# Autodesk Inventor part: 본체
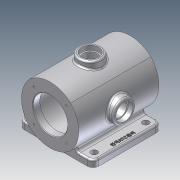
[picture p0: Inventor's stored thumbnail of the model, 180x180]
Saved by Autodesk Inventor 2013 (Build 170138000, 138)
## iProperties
Company: 한국ATC센터
Created: 2014-08
Part Number: 본체
Document SubType Name: Modeling
Designer: KYOUNG IL JANG
Density: 1 g/cm^3
Material: 일반
Mass: 1211.76 g
Surface Area: 1019.41 cm^2
Volume: 447.145 cm^3
Author: KYOUNG IL JANG
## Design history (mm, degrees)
sketch "스케치1"
  geometry: L1 (-50, 0)-(50, 0); L2 (-36.062, 36.062)-(36.062, 36.062); L3 (36.062, 36.062)-(36.062, -36.062); L4 (36.062, -36.062)-(-36.062, -36.062); L5 (-36.062, -36.062)-(-36.062, 36.062); A1 r 53.623 centre (-3.623, 0) between (36.062, -36.062) and (36.062, 36.062); A2 r 53.623 centre (3.623, 0) between (-36.062, 36.062) and (-36.062, -36.062); A3 r 53.623 centre (0, -3.623) between (36.062, 36.062) and (-36.062, 36.062); A4 r 53.623 centre (0, 3.623) between (-36.062, -36.062) and (36.062, -36.062); 4 further points
  constraints: 11 point on circle, 10 end point, 5 coincident, 4 centre point, 4 horizontal alignment, 3 equal radius, 2 horizontal, 2 parallel, 2 perpendicular, 1 midpoint
  dimensions: "d83" = 51 distance of L2.end point (0, 0); "d84" = 100 distance of L1.end L1.start
extrude "돌출1" new body sketch "스케치1" stored distance "d9" = 140; taper "d10" = 0 deg
node "작업 평면1"
sketch "스케치2"
  geometry: L1 (65, 60)-(-65, 60); L2 (-65, 60)-(-65, -60); L3 (-65, -60)-(65, -60); L4 (65, -60)-(65, 60); 4 further points
  constraints: 8 end point, 3 midpoint, 2 parallel, 2 vertical alignment, 1 horizontal, 1 horizontal alignment, 1 perpendicular
  dimensions: "d14" = 130 distance of L2.end L3.end; "d82" = 120 distance of L1.end L2.end
extrude "돌출2" join sketch "스케치2" distance "d15" = 12; taper "d16" = 0 deg
node "작업 평면3"
  node "작업 평면4"
sketch "스케치3"
  geometry: C1 r 20 at (0, 0); 1 further point
  constraints: 2 coincident, 1 centre point
  dimensions: "d19" = 40 diameter of C1
extrude "돌출3" join sketch "스케치3" stored distance "d23" = 12; taper "d24" = 0 deg
node "작업 평면6"
  node "작업 평면5"
sketch "스케치13"
  geometry: C1 r 20 at (0, 0); 1 further point
  constraints: 1 centre point, 1 coincident
  dimensions: "d88" = 40 diameter of C1
extrude "돌출7" join sketch "스케치13" stored distance "d89" = 10; taper "d90" = 0 deg
sketch "스케치4"
  geometry: C1 r 37.5 at (0, 0); 1 further point
  constraints: 1 centre point, 1 coincident
  dimensions: "d25" = 75 diameter of C1
extrude "돌출4" cut sketch "스케치4" stored distance "d26" = 116; taper "d27" = 0 deg
sketch "스케치5"
  geometry: C1 r 30 at (0, 0); 1 further point
  constraints: 1 centre point, 1 coincident
  dimensions: "d28" = 60 diameter of C1
extrude "돌출5" cut sketch "스케치5" stored distance "d29" = 116; taper "d30" = 0 deg
hole "구멍1" diameter "d33" = 25; stored, may be unused: countersink angle "d37" = 90 deg, drill point angle "d39" = 0 deg; dims "d31" = 10, "d32" = 10, "d34" = 6, "d35" = 30, "d36" = 8, "d38" = 40
hole "구멍4" diameter "d93" = 25; stored, may be unused: countersink angle "d97" = 90 deg, drill point angle "d99" = 118 deg; dims "d91" = 10, "d92" = 10, "d94" = 6, "d95" = 30, "d96" = 8, "d98" = 8
sketch "스케치6"
  geometry: L1 (-65, -60)-(-65, 60) reference; L2 (-65, 60)-(65, 60) reference; L3 (65, -60)-(-65, -60) reference; L4 (65, 60)-(65, -60) reference; L5 (0, -60)-(0, 60); L6 (-65, 0)-(65, 0); L7 (-52, -45)-(52, 45); C1 r 5.5 at (-52, -45); C2 r 5.5 at (-52, 45); C3 r 5.5 at (52, -45); C4 r 5.5 at (52, 45); 2 further points
  constraints: 6 end point, 6 midpoint, 4 centre point, 2 equal radius, 2 horizontal alignment, 2 vertical alignment
  dimensions: "d49" = 11 diameter of C1; "d50" = 11 diameter of C2; "d51" = 104 distance of L7.end C2.centre; "d52" = 90 distance of C3.centre L7.end
extrude "돌출6" cut sketch "스케치6" distance "d53" = 116; taper "d54" = 0 deg
sketch "스케치8"
  geometry: L1 (65, 60)-(65, -60) reference; 2 further points
  constraints: 1 horizontal alignment, 1 other
  dimensions: "d55" = 8 distance from line of L1 point (57, 0)
feature "엠보싱1" sketch "스케치8" dims "d27" = 0, "d57" = 1, "d58" = 0
fillet "모깎기2" dims "d60" = 5
fillet "모깎기5" dims "d63" = 10
fillet "모깎기6" dims "d64" = 3
fillet "모깎기7" dims "d65" = 3
sketch "스케치9"
  geometry: L1 (0, 0)-(-28.284, 28.284); L2 (0, 0)-(0, 40); C1 r 30 at (0, 0) reference; A1 r 40 centre (0, 0) between (-28.284, 28.284) and (0, 40); 1 further point
  constraints: 4 end point, 2 coincident, 2 point on circle, 1 centre point, 1 vertical
  dimensions: "d66" = 80 diameter of A1; "d67" = 45 deg angle of L1 L2
hole "M4" sketch "스케치9" at (-28.284, 28.284) diameter "d68" = 3.242; stored, may be unused: countersink angle "d72" = 90 deg, drill point angle "d74" = 118 deg; dims "d69" = 8, "d70" = 30, "d71" = 8, "d73" = 10
fillet "모깎기8" dims "d78" = 3
chamfer "모따기1" distance "d79" = 1; stored, may be unused: second distance "d80" = 2, angle "d81" = 45 deg
node "솔리드1"
pattern_circular "원형 패턴1" dims angle "d76" = 360 deg
mirror "대칭1"
other parameters: "d11" = -55
